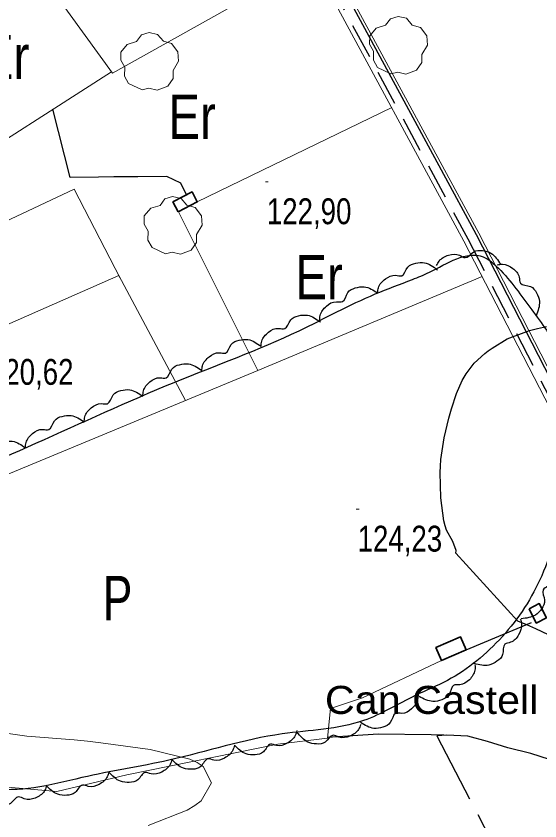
# Model space of a CAD drawing. Extents: x 487425 to 492029, y 4383576 to 4386788.
# Drawn here: x 490696.7 to 490873.9, y 4385746 to 4386018.5 of the extents above; entities that cross this region are included whole.
import ezdxf
from ezdxf.enums import TextEntityAlignment as Align

# ---------------------------------------------------------------- set-up
doc = ezdxf.new("R2010")
doc.units = 0
doc.header["$LTSCALE"] = 4
doc.linetypes.add('LONG_DASHED', pattern=[7.5, 6, -1.5])
doc.linetypes.add('MEDIUM_DASHED', pattern=[4.5, 3, -1.5])
for name, color, linetype, lineweight in [('25', 7, 'LONG_DASHED', 25), ('27', 7, 'Continuous', 25), ('29', 7, 'Continuous', 13), ('38', 7, 'Continuous', 25), ('47', 7, 'Continuous', 35), ('51', 7, 'Continuous', 13), ('7', 7, 'Continuous', 13), ('8', 7, 'Continuous', 25), ('9', 7, 'Continuous', 13)]:
    doc.layers.add(name, color=color, linetype=linetype, lineweight=lineweight)
doc.layers.add('31', color=7, linetype='Continuous')
doc.layers.add('5', color=7, linetype='Continuous')

msp = doc.modelspace()

# ---------------------------------------------------------------- linework, layer by layer
at = {"layer": '25'}
msp.add_line((490849, 4385803.92), (490872.35, 4385813.74), dxfattribs=at)
for points in [[(490754.39, 4385957.99), (490752.45, 4385961.97), (490747.66, 4385964.24), (490737.91, 4385964.04), (490729.81, 4385964.06), (490724.56, 4385964.01), (490714.97, 4385963.81), (490709.13, 4385986.97)], [(490841.41, 4385775), (490837.14, 4385775.17), (490819.22, 4385775.37), (490802.07, 4385774.28)], [(490900.97, 4385759.96), (490897.08, 4385760.44), (490885.02, 4385764.3), (490870.86, 4385768.84), (490863.07, 4385770.74), (490856.25, 4385772.93), (490849.51, 4385774.68), (490842.46, 4385775.08), (490839.01, 4385774.79), (490876.62, 4385702.93)]]:
    msp.add_lwpolyline(points, dxfattribs=at)
at = {"layer": '27'}
for points in [[(490660.05, 4385855.1), (490703.37, 4385873.87), (490750.22, 4385894.5), (490792.49, 4385911.99), (490818.24, 4385924.43), (490830.85, 4385929.34), (490836.56, 4385931.8), (490854.72, 4385936.99), (490859.88, 4385933.16), (490871.16, 4385919.1), (490876.17, 4385912.11), (490877.21, 4385910.46), (490879.3, 4385906.33), (490885.89, 4385880.82), (490884.04, 4385864.03), (490878.8, 4385841.4), (490874.56, 4385829.04), (490861.23, 4385808.46), (490842.67, 4385793.59), (490831.78, 4385788.45), (490814.21, 4385779.96), (490786.75, 4385775.47), (490748.41, 4385766.59), (490719, 4385760.68), (490702.72, 4385757.2), (490672.43, 4385758.79), (490653.1, 4385762.68), (490611.42, 4385765.65), (490603.32, 4385766.65), (490588.54, 4385786.41), (490581.15, 4385798.73), (490578.77, 4385803.76), (490571.76, 4385817.36), (490565.66, 4385831.4), (490588.65, 4385849.1), (490606.09, 4385862.69), (490620.44, 4385872.92), (490631.86, 4385880.46), (490636.74, 4385882.47), (490642.06, 4385882.38), (490647.37, 4385876.74), (490655.35, 4385862.84), (490658.4, 4385856.01)], [(490838.97, 4385934.02), (490839.83, 4385935.57), (490843.06, 4385937.57), (490846.75, 4385937.55), (490848.63, 4385936.72), (490851.54, 4385938.74), (490854.51, 4385939.11), (490857.38, 4385938.18), (490860.67, 4385934.46)], [(490819.02, 4385924.79), (490819.31, 4385926.54), (490821.65, 4385929.52), (490825.14, 4385930.74), (490827.19, 4385930.6), (490829.24, 4385933.5), (490831.91, 4385934.85), (490834.93, 4385934.96), (490839.27, 4385932.57)], [(490859.47, 4385934.27), (490861.23, 4385934.49), (490864.76, 4385933.09), (490866.92, 4385930.1), (490867.37, 4385928.1), (490870.74, 4385926.95), (490872.79, 4385924.79), (490873.76, 4385921.92), (490872.71, 4385917.07)], [(490799.46, 4385915.38), (490799.61, 4385917.15), (490801.7, 4385920.31), (490805.07, 4385921.81), (490807.13, 4385921.84), (490808.94, 4385924.9), (490811.48, 4385926.46), (490814.49, 4385926.82), (490819.01, 4385924.79)], [(490779.59, 4385906.68), (490779.84, 4385908.44), (490782.12, 4385911.47), (490785.57, 4385912.78), (490787.62, 4385912.68), (490789.61, 4385915.63), (490792.24, 4385917.04), (490795.26, 4385917.22), (490799.66, 4385914.93)], [(490759.54, 4385898.38), (490759.79, 4385900.14), (490762.05, 4385903.18), (490765.5, 4385904.5), (490767.55, 4385904.41), (490769.53, 4385907.36), (490772.16, 4385908.78), (490775.17, 4385908.97), (490779.58, 4385906.7)], [(490739.6, 4385889.82), (490739.81, 4385891.58), (490742.01, 4385894.67), (490745.43, 4385896.06), (490747.48, 4385896.01), (490749.4, 4385899.01), (490751.99, 4385900.48), (490755.01, 4385900.74), (490759.46, 4385898.57)], [(490719.75, 4385881.06), (490719.96, 4385882.82), (490722.16, 4385885.91), (490725.58, 4385887.3), (490727.63, 4385887.26), (490729.54, 4385890.25), (490732.14, 4385891.73), (490735.15, 4385891.98), (490739.61, 4385889.81)], [(490699.88, 4385872.34), (490700.09, 4385874.1), (490702.29, 4385877.19), (490705.71, 4385878.57), (490707.77, 4385878.52), (490709.68, 4385881.52), (490712.28, 4385882.99), (490715.3, 4385883.24), (490719.75, 4385881.06)], [(490679.97, 4385863.7), (490680.19, 4385865.47), (490682.4, 4385868.54), (490685.83, 4385869.91), (490687.89, 4385869.86), (490689.81, 4385872.84), (490692.42, 4385874.3), (490695.43, 4385874.54), (490699.88, 4385872.34)], [(490876.93, 4385834.06), (490877.93, 4385832.59), (490878.29, 4385828.82), (490876.62, 4385825.53), (490875.04, 4385824.22), (490875.55, 4385820.7), (490874.55, 4385817.89), (490872.45, 4385815.72), (490867.65, 4385814.45)], [(490867.31, 4385814.37), (490867.73, 4385812.65), (490866.75, 4385808.98), (490864.02, 4385806.49), (490862.08, 4385805.82), (490861.33, 4385802.34), (490859.41, 4385800.06), (490856.68, 4385798.77), (490851.74, 4385799.26)], [(490851.97, 4385798.88), (490851.94, 4385797.1), (490850.07, 4385793.8), (490846.81, 4385792.08), (490844.76, 4385791.91), (490843.16, 4385788.74), (490840.73, 4385787.01), (490837.75, 4385786.45), (490833.1, 4385788.16)], [(490832.71, 4385788.91), (490832.58, 4385787.14), (490830.52, 4385783.96), (490827.16, 4385782.42), (490825.1, 4385782.38), (490823.32, 4385779.31), (490820.79, 4385777.72), (490817.79, 4385777.34), (490813.25, 4385779.32)], [(490813.32, 4385778.65), (490812.61, 4385777.02), (490809.6, 4385774.71), (490805.92, 4385774.38), (490803.97, 4385775.02), (490801.27, 4385772.72), (490798.35, 4385772.06), (490795.4, 4385772.7), (490791.77, 4385776.08)], [(490791.67, 4385776.63), (490791.15, 4385774.94), (490788.42, 4385772.3), (490784.81, 4385771.56), (490782.79, 4385771.98), (490780.37, 4385769.38), (490777.55, 4385768.4), (490774.54, 4385768.7), (490770.55, 4385771.65)], [(490770.56, 4385771.61), (490770.02, 4385769.92), (490767.27, 4385767.31), (490763.65, 4385766.6), (490761.64, 4385767.04), (490759.19, 4385764.46), (490756.36, 4385763.51), (490753.35, 4385763.83), (490749.39, 4385766.82)], [(490749.4, 4385766.79), (490748.82, 4385765.11), (490746.01, 4385762.57), (490742.37, 4385761.94), (490740.38, 4385762.43), (490737.87, 4385759.91), (490735.01, 4385759.03), (490732.02, 4385759.43), (490728.13, 4385762.51)], [(490728.1, 4385762.65), (490727.54, 4385760.96), (490724.77, 4385758.38), (490721.14, 4385757.7), (490719.14, 4385758.16), (490716.66, 4385755.61), (490713.82, 4385754.69), (490710.82, 4385755.04), (490706.89, 4385758.07)], [(490706.96, 4385757.64), (490706.22, 4385756.02), (490703.17, 4385753.76), (490699.49, 4385753.49), (490697.55, 4385754.17), (490694.81, 4385751.9), (490691.88, 4385751.3), (490688.94, 4385751.98), (490685.37, 4385755.43)]]:
    msp.add_spline(points, degree=3, dxfattribs=at)
at = {"layer": '29'}
for points in [[(490823.54, 4385998.97), (490819, 4386001.09), (490817.59, 4386003.63), (490817.69, 4386006.61), (490816.32, 4386009.02), (490816.36, 4386011.77), (490818.52, 4386014.37), (490821.71, 4386015.37), (490823.36, 4386017.56), (490825.93, 4386018.39), (490828.79, 4386017.74), (490830.74, 4386015.47), (490833.55, 4386014.65), (490835.68, 4386011.8), (490835.92, 4386008.67), (490834.04, 4386005.52), (490834.04, 4386002.84), (490832.22, 4386000.23), (490828.6, 4385998.89), (490825.83, 4385999.52)], [(490739.33, 4385993.53), (490734.79, 4385995.65), (490733.38, 4385998.19), (490733.48, 4386001.17), (490732.11, 4386003.58), (490732.15, 4386006.33), (490734.31, 4386008.93), (490737.5, 4386009.93), (490739.15, 4386012.12), (490741.72, 4386012.95), (490744.58, 4386012.3), (490746.53, 4386010.03), (490749.34, 4386009.21), (490751.47, 4386006.36), (490751.71, 4386003.23), (490749.83, 4386000.08), (490749.83, 4385997.4), (490748.01, 4385994.79), (490744.39, 4385993.45), (490741.62, 4385994.08)], [(490747.26, 4385938.02), (490742.72, 4385940.14), (490741.31, 4385942.68), (490741.41, 4385945.66), (490740.04, 4385948.07), (490740.08, 4385950.82), (490742.24, 4385953.42), (490745.43, 4385954.42), (490747.08, 4385956.61), (490749.65, 4385957.44), (490752.51, 4385956.79), (490754.46, 4385954.52), (490757.27, 4385953.7), (490759.4, 4385950.85), (490759.64, 4385947.72), (490757.76, 4385944.57), (490757.76, 4385941.89), (490755.94, 4385939.28), (490752.32, 4385937.94), (490749.55, 4385938.57)]]:
    msp.add_lwpolyline(points, close=True, dxfattribs=at)
at = {"layer": '38'}
msp.add_lwpolyline([(490698.82, 4386334.95), (490725.22, 4386282.97), (490747.72, 4386237.85), (490777.23, 4386181.53), (490823.16, 4386093.37), (490836.87, 4386066.35), (490838.17, 4386062.14), (490838.06, 4386060.74), (490837.68, 4386059.73), (490837.11, 4386058.09), (490836.91, 4386057.3), (490836.19, 4386056.22), (490832.79, 4386053.49), (490823.06, 4386047.3), (490807.58, 4386038.73), (490806.77, 4386037.93), (490805.27, 4386036.3), (490805.18, 4386036.07), (490805.04, 4386035.45), (490804.76, 4386034.44), (490804.71, 4386033.8), (490805, 4386032.28), (490852.4, 4385944.53), (490894.37, 4385862.9)], dxfattribs=at)
at = {"layer": '38', "linetype": 'MEDIUM_DASHED'}
msp.add_lwpolyline([(490798.08, 4386134.64), (490820.34, 4386091.91), (490833.91, 4386065.16), (490834.95, 4386061.78), (490834.92, 4386061.44), (490834.69, 4386060.81), (490834.06, 4386059), (490833.96, 4386058.61), (490833.82, 4386058.4), (490830.93, 4386056.08), (490821.43, 4386050.03), (490805.65, 4386041.3), (490804.48, 4386040.14), (490802.5, 4386037.99), (490802.13, 4386036.98), (490801.95, 4386036.23), (490801.62, 4386034.99), (490801.51, 4386033.63), (490801.97, 4386031.2), (490849.59, 4385943.05), (490891.56, 4385861.42), (490957.57, 4385739.53), (490961.18, 4385729.85), (490962.91, 4385716.19)], dxfattribs=at)
at = {"layer": '47'}
for points in [[(490751.52, 4385952.23), (490758.01, 4385955.6), (490756.26, 4385958.96), (490749.77, 4385955.59)], [(490870.26, 4385817.81), (490872.71, 4385813.02), (490876.17, 4385814.79), (490873.72, 4385819.58)], [(490849, 4385803.92), (490840.65, 4385800.29), (490838.73, 4385804.7), (490847.08, 4385808.33)]]:
    msp.add_lwpolyline(points, close=True, dxfattribs=at)
at = {"layer": '51'}
for p, q in [((490758.01, 4385955.6), (490823.83, 4385987.57)), ((490813.86, 4385787.68), (490840.65, 4385800.29))]:
    msp.add_line(p, q, dxfattribs=at)
for points in [[(490699.66, 4386335.38), (490726.07, 4386283.4), (490748.56, 4386238.28), (490778.07, 4386181.97), (490824, 4386093.8), (490837.75, 4386066.71), (490839.13, 4386062.25), (490839, 4386060.53), (490838.57, 4386059.41), (490838.02, 4386057.82), (490837.79, 4386056.91), (490836.9, 4386055.57), (490833.34, 4386052.72), (490823.54, 4386046.48), (490808.15, 4386037.96), (490807.45, 4386037.27), (490806.09, 4386035.79), (490806.09, 4386035.79), (490805.96, 4386035.22), (490805.7, 4386034.27), (490805.67, 4386033.85), (490805.9, 4386032.6), (490853.24, 4385944.97), (490895.21, 4385863.34)], [(490797.24, 4386132.97), (490818.99, 4386091.22), (490832.5, 4386064.59), (490833.41, 4386061.62), (490833.43, 4386061.77), (490833.26, 4386061.32), (490832.61, 4386059.44), (490832.55, 4386059.24), (490832.69, 4386059.44), (490830.04, 4386057.32), (490820.65, 4386051.34), (490804.73, 4386042.53), (490803.39, 4386041.19), (490801.18, 4386038.8), (490800.67, 4386037.42), (490800.48, 4386036.6), (490800.12, 4386035.25), (490799.98, 4386033.55), (490800.52, 4386030.69), (490848.25, 4385942.34), (490890.22, 4385860.71), (490956.19, 4385738.9), (490957.94, 4385734.24)], [(490657.81, 4386106.59), (490669.97, 4386085.19), (490684.07, 4386061.98), (490704.83, 4386033.05), (490729.32, 4385999.16), (490798.94, 4386038.24)], [(490728.95, 4385999.68), (490672.6, 4385963.56), (490616.25, 4385926.77), (490609.38, 4385937.98)], [(490731.96, 4385929.72), (490716.3, 4385959.91), (490682.93, 4385944.26)], [(490751.62, 4385952.28), (490778.5, 4385898.54), (490854.44, 4385930.32)], [(490638.63, 4385889.79), (490731.44, 4385930.69), (490753.99, 4385888.38)], [(490778.5, 4385898.54), (490661.54, 4385850), (490644.68, 4385880.04), (490626.18, 4385909.79)], [(490813.86, 4385787.68), (490803.12, 4385784.04), (490802.04, 4385774.07), (490785.24, 4385771.95), (490734.22, 4385761.61), (490710.44, 4385755.98), (490677.08, 4385758.93), (490647.7, 4385762.02), (490611.64, 4385763.85), (490602.94, 4385764.4), (490564.05, 4385831.4)]]:
    msp.add_lwpolyline(points, dxfattribs=at)
at = {"layer": '7'}
for p, q in [((490781.04, 4385962.41), (490782.04, 4385962.41)), ((490811.75, 4385851.57), (490812.75, 4385851.57))]:
    msp.add_line(p, q, dxfattribs=at)
at = {"layer": '8'}
msp.add_lwpolyline([(490883.27, 4385805.99), (490872.58, 4385811.08), (490869.56, 4385812.37), (490866.51, 4385813.61), (490845.47, 4385836.64), (490845.62, 4385837.6), (490844.46, 4385840.6), (490842.31, 4385844.45), (490841.84, 4385845.96), (490841.43, 4385847.65), (490840.4, 4385855.36), (490840.16, 4385863.93), (490840.26, 4385866.17), (490840.41, 4385868.35), (490841.55, 4385875.75), (490843.15, 4385882.32), (490843.6, 4385883.97), (490844.05, 4385885.56), (490845.7, 4385890.73), (490847.65, 4385895.16), (490848.28, 4385896.3), (490848.96, 4385897.39), (490851.75, 4385900.97), (490855.32, 4385904.26), (490856.49, 4385905.16), (490857.74, 4385906.06), (490862.9, 4385909.25), (490870.4, 4385912.08), (490873.12, 4385912.75), (490876.12, 4385913.36)], dxfattribs=at)
at = {"layer": '9'}
msp.add_lwpolyline([(490741.38, 4385744.42), (490754.62, 4385749.66), (490757.18, 4385751.21), (490759.28, 4385752.8), (490762.86, 4385758.88), (490759.97, 4385764.48), (490757.97, 4385765.77), (490755.45, 4385766.95), (490742.04, 4385770.25), (490725.43, 4385772.49), (490720.9, 4385772.99), (490716.39, 4385773.45), (490700.34, 4385774.67), (490686.85, 4385776.61)], dxfattribs=at)

# ---------------------------------------------------------------- texts
at = {"layer": '31'}
for s, width, p in [('Er', 0.8, (490693.15, 4385997.15)), ('Er', 0.8, (490756.29, 4385976.94)), ('Er', 0.8, (490799.23, 4385922.61)), ('P', 0.75, (490731.03, 4385813.95))]:
    msp.add_text(s, height=15, dxfattribs=dict(at, width=width)).set_placement(p, align=Align.CENTER)
at = {"layer": '5', "width": 1.1}
msp.add_text('Can Castell', height=9.5, dxfattribs=at).set_placement((490873.43, 4385782.23), align=Align.RIGHT)
at = {"layer": '7', "width": 0.8}
for s, p in [('122,90', (490781.54, 4385948.04)), ('120,62', (490687.5, 4385893.66)), ('124,23', (490812.25, 4385837.2))]:
    msp.add_text(s, height=8.75, dxfattribs=at).set_placement(p)

doc.saveas('drawing.dxf')
